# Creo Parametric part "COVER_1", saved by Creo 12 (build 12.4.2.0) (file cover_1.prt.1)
Units: Custom; MM, KILOGRAM, SECS

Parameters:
  PTC_WM_ITERATION = "0"
  PTC_WM_VERSION = "-.0"
  PTC_WM_LIFECYCLE_STATE = "In Work"
  PTC_WM_LIFECYCLE = "MO_CADDocument"
  PTC_WM_CREATED_BY = "Maximilian Roepper (Z0017RMS: MO)"
  PTC_WM_CREATED_ON = "18-Sep-26 11:36:42 AM"
  PTC_WM_MODIFIED_BY = "Maximilian Roepper (Z0017RMS: MO)"
  PTC_WM_MODIFIED_ON = "18-Sep-26 11:36:46 AM"
  PDMLINKNUMBER = "PDM000071455287"
  PTC_WM_NAME = "cover_1.prt"
  PTC_WM_NUMBER = "PDM000071455287"

Other parameters: WEIGHT, WEIGHT_FACTOR, WEIGHT_ADD, _MASS_TEMP, _DIFF_TEMP, MC_ERRORS, SUPPLIER

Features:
  1. coordinate system
  2. datum plane "PRT_YZ"
  3. datum plane "PRT_XY"
  4. datum plane "PRT_XZ"
  5. coordinate system
  6. datum axis
  7. datum axis
  8. datum axis
  9. coordinate system
  10. imported feature

Other named items: PRT, SIEMENS_MO, DRW_VIEW_ORG, PRT_X, PRT_Y, PRT_Z, CS0, ROUGH_GROB

Layers: 00_STD_CSYS-KSYS, 01_STD_PLANES-EBENEN, 02_STD_AXES-ACHSEN, 03_STD_CSYS-KSYS, 24_IMPORT_FEAT-IMPORT_KE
